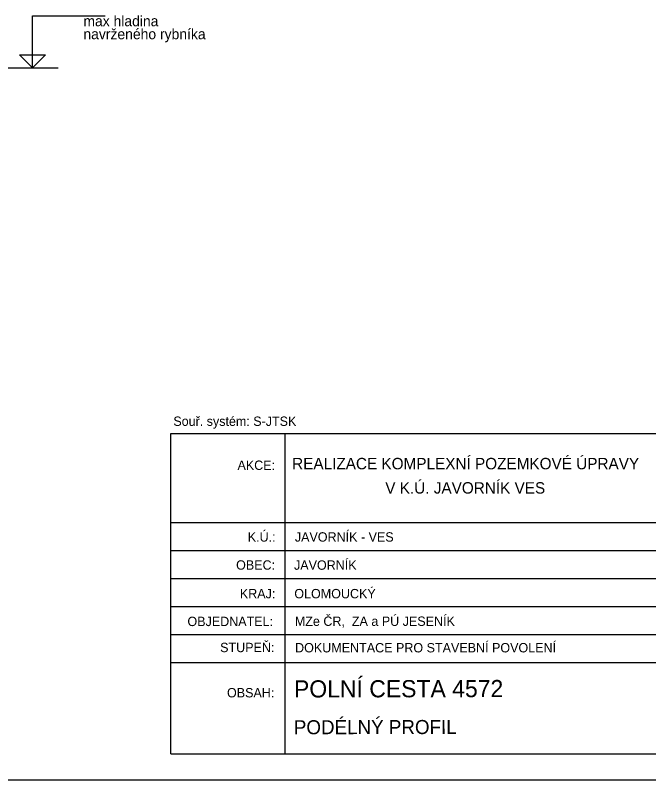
# Model space of a CAD drawing. Extents: x -552393 to -551553, y -1030378 to -1030070.
# Drawn here: x -551742.7 to -551620.9, y -1030367.5 to -1030220.5 of the extents above; entities that cross this region are included whole.
import ezdxf

# ---------------------------------------------------------------- set-up
doc = ezdxf.new("R2010")
doc.units = 0
for name, color, linetype in [('14', 7, 'Continuous'), ('16', 7, 'Continuous'), ('60', 7, 'Continuous'), ('8', 7, 'Continuous')]:
    doc.layers.add(name, color=color, linetype=linetype)

msp = doc.modelspace()

# ---------------------------------------------------------------- linework, layer by layer
at = {"layer": '14'}
msp.add_line((-551748.56, -1030230.64), (-551734.41, -1030230.64), dxfattribs=at)
at = {"layer": '16'}
msp.add_lwpolyline([(-551739.4, -1030230.64), (-551739.4, -1030220.64), (-551725.4, -1030220.64)], dxfattribs=at)
at = {"layer": '60'}
for p, q in [((-551712.77, -1030300.96), (-551557.77, -1030300.96)), ((-551712.77, -1030362.51), (-551712.77, -1030300.96)), ((-551690.84, -1030362.51), (-551690.84, -1030300.96)), ((-551712.77, -1030318.03), (-551557.77, -1030318.03)), ((-551712.77, -1030323.42), (-551557.77, -1030323.42)), ((-551712.77, -1030328.81), (-551557.77, -1030328.81)), ((-551712.77, -1030334.2), (-551557.77, -1030334.2)), ((-551712.77, -1030339.59), (-551557.77, -1030339.59)), ((-551712.77, -1030344.98), (-551572.66, -1030344.98)), ((-551712.77, -1030362.51), (-551557.77, -1030362.51)), ((-552392.77, -1030367.51), (-551552.77, -1030367.51))]:
    msp.add_line(p, q, dxfattribs=at)
at = {"layer": '8'}
for p, q in [((-551741.9, -1030228.14), (-551736.9, -1030228.14)), ((-551739.4, -1030230.64), (-551741.9, -1030228.14)), ((-551736.9, -1030228.14), (-551739.4, -1030230.64))]:
    msp.add_line(p, q, dxfattribs=at)

# ---------------------------------------------------------------- texts
at = {"layer": '14'}
for s, p in [('max hladina', (-551729.59, -1030222.64)), ('navrženého rybníka', (-551729.59, -1030225.14))]:
    msp.add_text(s, height=2, dxfattribs=at).set_placement(p)
at = {"layer": '60'}
for s, height, rotation, p in [('Souř. systém: S-JTSK', 1.7971, 0, (-551712.3, -1030299.48)), ('REALIZACE KOMPLEXNÍ POZEMKOVÉ ÚPRAVY', 2.2, 0, (-551689.47, -1030307.83)), ('AKCE:', 1.797, 0, (-551699.97, -1030307.94)), (' V K.Ú. JAVORNÍK VES', 2.2, 0, (-551672.38, -1030312.5)), ('K.Ú.:', 1.8, 0, (-551698, -1030321.73)), ('JAVORNÍK - VES', 1.8, 0, (-551688.95, -1030321.73)), ('OBEC:', 1.8, 0, (-551700.24, -1030327.12)), ('JAVORNÍK', 1.8, 0, (-551689.11, -1030327.14)), ('KRAJ:', 1.8, 0, (-551699.52, -1030332.63)), ('OLOMOUCKÝ', 1.8, 0, (-551689.05, -1030332.63)), ('MZe ČR,  ZA a PÚ JESENÍK', 1.8, 0, (-551688.95, -1030337.93)), ('OBJEDNATEL:', 1.8, 0, (-551709.59, -1030337.97)), ('STUPEŇ:', 1.8, 0, (-551703.31, -1030342.98)), ('DOKUMENTACE PRO STAVEBNÍ POVOLENÍ', 1.8, 0, (-551688.9, -1030343.03)), ('POLNÍ CESTA 4572', 3.3, 0.1038, (-551689.11, -1030351.7)), ('OBSAH:', 1.8, 0, (-551701.99, -1030351.68)), ('PODÉLNÝ PROFIL', 2.7, 0.1038, (-551689.14, -1030358.77))]:
    msp.add_text(s, height=height, rotation=rotation, dxfattribs=at).set_placement(p)

doc.saveas('drawing.dxf')
